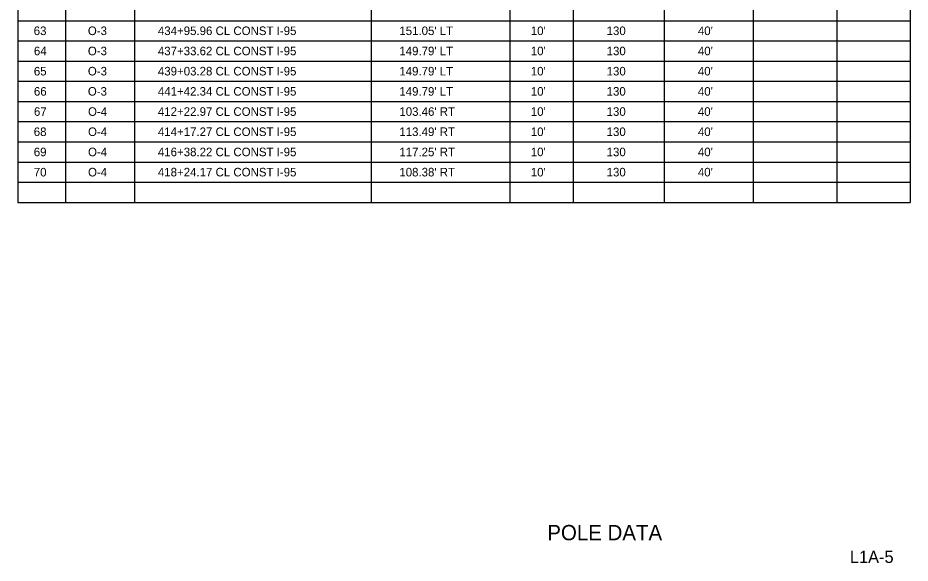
# Model space of a CAD drawing. Extents: x -816.7 to -727.6, y -2197.9 to -2187.8.
# Drawn here: x -808.11 to -800.82, y -2197.64 to -2193.19 of the extents above; entities that cross this region are included whole.
import ezdxf

# ---------------------------------------------------------------- set-up
doc = ezdxf.new("R2010")
doc.units = 0
for name, color, linetype in [('ClipBorder_dp', 7, 'Continuous'), ('MatchLines_dp', 7, 'Continuous'), ('NorthArw_dp', 7, 'Continuous'), ('Scale_dp', 7, 'Continuous'), ('SignWorkZone', 7, 'Continuous'), ('TextLabel', 7, 'Continuous')]:
    doc.layers.add(name, color=color, linetype=linetype)

msp = doc.modelspace()

# ---------------------------------------------------------------- linework, layer by layer
at = {"layer": 'MatchLines_dp'}
for p, q in [((-808.1136, -2193.2123), (-800.8236, -2193.2123)), ((-808.1136, -2193.2123), (-800.8236, -2193.2123)), ((-808.1136, -2193.3773), (-800.8236, -2193.3773)), ((-808.1136, -2193.3773), (-800.8236, -2193.3773)), ((-808.1136, -2193.5423), (-800.8236, -2193.5423)), ((-808.1136, -2193.5423), (-800.8236, -2193.5423)), ((-808.1136, -2193.7073), (-800.8236, -2193.7073)), ((-808.1136, -2193.7073), (-800.8236, -2193.7073)), ((-808.1136, -2193.8723), (-800.8236, -2193.8723)), ((-808.1136, -2193.8723), (-800.8236, -2193.8723)), ((-808.1136, -2194.0373), (-800.8236, -2194.0373)), ((-808.1136, -2194.0373), (-800.8236, -2194.0373)), ((-808.1136, -2194.2023), (-800.8236, -2194.2023)), ((-808.1136, -2194.2023), (-800.8236, -2194.2023)), ((-808.1136, -2194.3673), (-800.8236, -2194.3673)), ((-808.1136, -2194.3673), (-800.8236, -2194.3673)), ((-808.1136, -2194.5323), (-800.8236, -2194.5323)), ((-808.1136, -2194.5323), (-800.8236, -2194.5323))]:
    msp.add_line(p, q, dxfattribs=at)
at = {"layer": 'NorthArw_dp'}
for p, q in [((-808.1136, -2188.0973), (-808.1136, -2194.6973)), ((-800.8236, -2188.0973), (-800.8236, -2194.6973)), ((-808.1136, -2194.6973), (-800.8236, -2194.6973))]:
    msp.add_line(p, q, dxfattribs=at)
at = {"layer": 'Scale_dp'}
for p, q in [((-807.7236, -2188.4273), (-807.7236, -2194.6973)), ((-807.7236, -2188.4273), (-807.7236, -2194.6973)), ((-807.1611, -2188.4273), (-807.1611, -2194.6973)), ((-807.1611, -2188.4273), (-807.1611, -2194.6973)), ((-805.2261, -2188.4273), (-805.2261, -2194.6973)), ((-804.0936, -2188.4273), (-804.0936, -2194.5323)), ((-804.0936, -2188.4273), (-804.0936, -2194.6973)), ((-803.5761, -2188.4273), (-803.5761, -2194.5323)), ((-803.5761, -2188.4273), (-803.5761, -2194.6973)), ((-802.8336, -2188.4273), (-802.8336, -2194.6973)), ((-802.8336, -2188.4273), (-802.8336, -2194.6973)), ((-802.1061, -2188.4273), (-802.1061, -2194.6973)), ((-802.1061, -2188.4273), (-802.1061, -2194.6973)), ((-801.4236, -2188.4273), (-801.4236, -2194.6973)), ((-805.2261, -2188.9223), (-805.2261, -2194.6973))]:
    msp.add_line(p, q, dxfattribs=at)

# ---------------------------------------------------------------- texts
at = {"layer": 'ClipBorder_dp'}
for s, p in [('63', (-807.9839, -2193.3298)), ('O-3', (-807.5415, -2193.3298)), ('434+95.96 CL CONST I-95', (-806.9694, -2193.3298)), ("151.05' LT", (-804.9968, -2193.3298)), ("10'", (-803.9228, -2193.3298)), ('130', (-803.3034, -2193.3298)), ("40'", (-802.5578, -2193.3298)), ('64', (-807.9825, -2193.4948)), ('O-3', (-807.5415, -2193.4948)), ('437+33.62 CL CONST I-95', (-806.9694, -2193.4948)), ("149.79' LT", (-804.9968, -2193.4948)), ("10'", (-803.9228, -2193.4948)), ('130', (-803.3034, -2193.4948)), ("40'", (-802.5578, -2193.4948)), ('65', (-807.983, -2193.6598)), ('O-3', (-807.5415, -2193.6598)), ('439+03.28 CL CONST I-95', (-806.9694, -2193.6598)), ("149.79' LT", (-804.9968, -2193.6598)), ("10'", (-803.9228, -2193.6598)), ('130', (-803.3034, -2193.6598)), ("40'", (-802.5578, -2193.6598)), ('66', (-807.9825, -2193.8248)), ('O-3', (-807.5415, -2193.8248)), ('441+42.34 CL CONST I-95', (-806.9694, -2193.8248)), ("149.79' LT", (-804.9968, -2193.8248)), ("10'", (-803.9228, -2193.8248)), ('130', (-803.3034, -2193.8248)), ("40'", (-802.5578, -2193.8248)), ('67', (-807.9819, -2193.9898)), ('O-4', (-807.5401, -2193.9898)), ('412+22.97 CL CONST I-95', (-806.9694, -2193.9898)), ("103.46' RT", (-804.9968, -2193.9898)), ("10'", (-803.9228, -2193.9898)), ('130', (-803.3034, -2193.9898)), ("40'", (-802.5578, -2193.9898)), ('68', (-807.9836, -2194.1548)), ('O-4', (-807.5401, -2194.1548)), ('414+17.27 CL CONST I-95', (-806.9694, -2194.1548)), ("113.49' RT", (-804.9968, -2194.1548)), ("10'", (-803.9228, -2194.1548)), ('130', (-803.3034, -2194.1548)), ("40'", (-802.5578, -2194.1548)), ('69', (-807.9835, -2194.3198)), ('O-4', (-807.5401, -2194.3198)), ('416+38.22 CL CONST I-95', (-806.9694, -2194.3198)), ("117.25' RT", (-804.9968, -2194.3198)), ("10'", (-803.9228, -2194.3198)), ('130', (-803.3034, -2194.3198)), ("40'", (-802.5578, -2194.3198)), ('70', (-807.9833, -2194.4848)), ('O-4', (-807.5401, -2194.4848)), ('418+24.17 CL CONST I-95', (-806.9694, -2194.4848)), ("108.38' RT", (-804.9968, -2194.4848)), ("10'", (-803.9228, -2194.4848)), ('130', (-803.3034, -2194.4848)), ("40'", (-802.5578, -2194.4848))]:
    msp.add_text(s, height=0.07, dxfattribs=at).set_placement(p)
at = {"layer": 'SignWorkZone'}
msp.add_text('L1A-5 ', height=0.1, dxfattribs=at).set_placement((-801.3158, -2197.6434))
at = {"layer": 'TextLabel'}
msp.add_text('POLE DATA', height=0.125, dxfattribs=at).set_placement((-803.788, -2197.4577))

doc.saveas('drawing.dxf')
